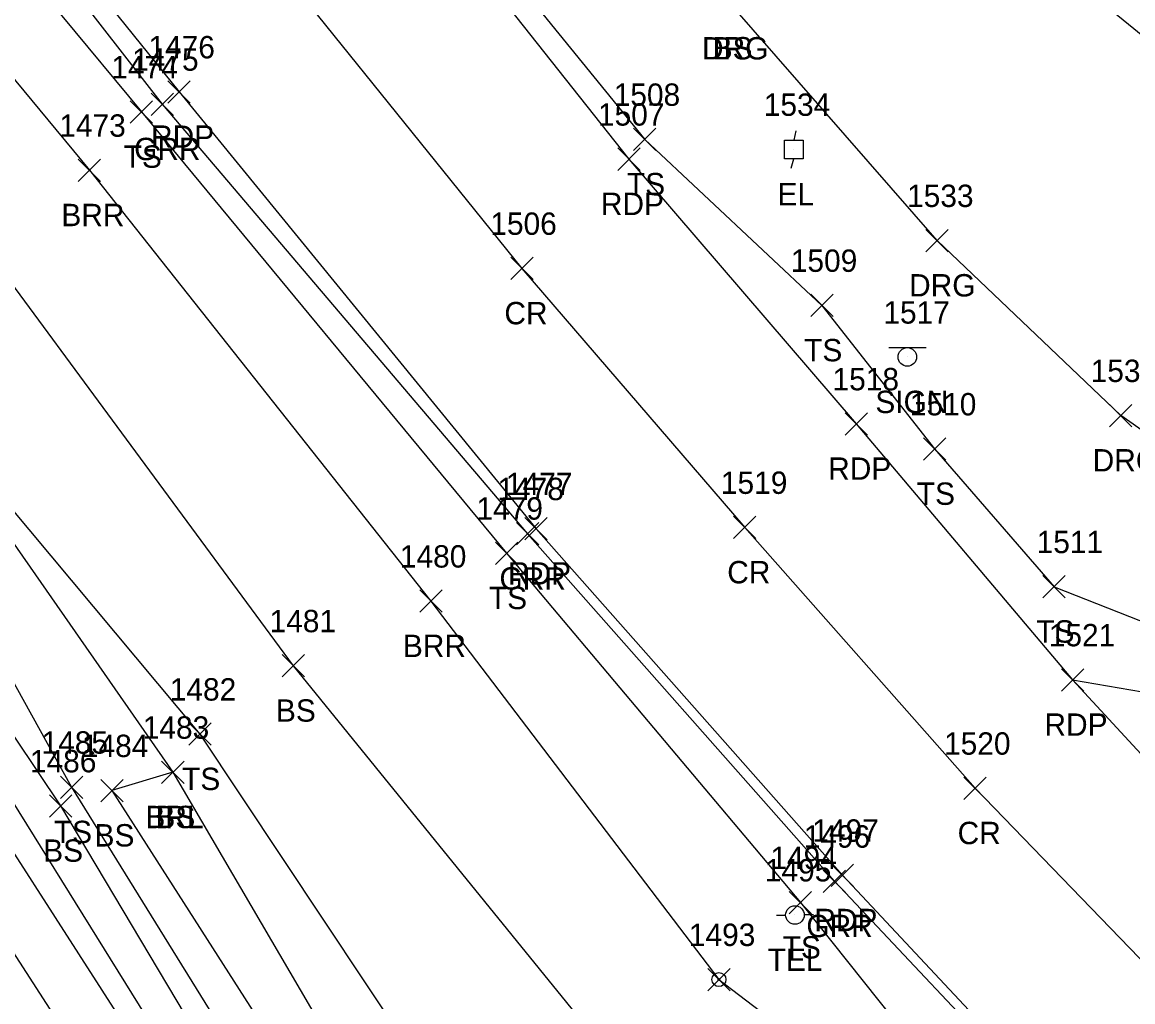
# Model space of a CAD drawing. Extents: x 1505656 to 1508446, y 700805 to 703031.
# Drawn here: x 1506356.7 to 1506456, y 702000.4 to 702088 of the extents above; entities that cross this region are included whole.
import ezdxf

# ---------------------------------------------------------------- set-up
doc = ezdxf.new("R2010")
doc.units = 0
for name, color, linetype in [('L_A', 7, 'Continuous'), ('L_I', 7, 'Continuous'), ('L_TIC', 7, 'Continuous'), ('LABL', 7, 'Continuous'), ('LELB', 7, 'Continuous'), ('P_A', 7, 'Continuous'), ('P_I', 7, 'Continuous'), ('P_TIC', 7, 'Continuous'), ('PET', 7, 'Continuous'), ('PRC', 7, 'Continuous'), ('R_A', 7, 'Continuous'), ('R_I', 7, 'Continuous'), ('R_TIC', 7, 'Continuous'), ('RDG', 7, 'Continuous'), ('RGR', 7, 'Continuous'), ('RR', 7, 'Continuous'), ('RRB', 7, 'Continuous'), ('S_A', 7, 'Continuous'), ('S_I', 7, 'Continuous'), ('SSGN', 7, 'Continuous'), ('U_A', 7, 'Continuous'), ('U_I', 7, 'Continuous'), ('UEPT', 7, 'Continuous'), ('UP', 7, 'Continuous'), ('UPGW', 7, 'Continuous')]:
    doc.layers.add(name, color=color, linetype=linetype)

msp = doc.modelspace()

# ---------------------------------------------------------------- linework, layer by layer
at = {"layer": 'L_TIC'}
for points in [[(1506366.336, 702078.99), (1506368.336, 702080.99)], [(1506368.336, 702078.99), (1506366.336, 702080.99)], [(1506411.366, 702076.53), (1506413.366, 702078.53)], [(1506413.366, 702076.53), (1506411.366, 702078.53)], [(1506361.684, 702073.768), (1506363.684, 702075.768)], [(1506363.684, 702073.768), (1506361.684, 702075.768)], [(1506427.221, 702061.685), (1506429.221, 702063.685)], [(1506429.221, 702061.685), (1506427.221, 702063.685)], [(1506437.306, 702048.851), (1506439.306, 702050.851)], [(1506439.306, 702048.851), (1506437.306, 702050.851)], [(1506399.017, 702039.528), (1506401.017, 702041.528)], [(1506401.017, 702039.528), (1506399.017, 702041.528)], [(1506447.995, 702036.533), (1506449.995, 702038.533)], [(1506449.995, 702036.533), (1506447.995, 702038.533)], [(1506392.244, 702035.244), (1506394.244, 702037.244)], [(1506394.244, 702035.244), (1506392.244, 702037.244)], [(1506379.93, 702029.463), (1506381.93, 702031.463)], [(1506381.93, 702029.463), (1506379.93, 702031.463)], [(1506371.567, 702023.35), (1506373.567, 702025.35)], [(1506373.567, 702023.35), (1506371.567, 702025.35)], [(1506369.149, 702019.942), (1506371.149, 702021.942)], [(1506371.149, 702019.942), (1506369.149, 702021.942)], [(1506369.149, 702019.942), (1506371.149, 702021.942)], [(1506371.149, 702019.942), (1506369.149, 702021.942)], [(1506360.093, 702018.604), (1506362.093, 702020.604)], [(1506362.093, 702018.604), (1506360.093, 702020.604)], [(1506363.703, 702018.302), (1506365.703, 702020.302)], [(1506365.703, 702018.302), (1506363.703, 702020.302)], [(1506359.109, 702016.936), (1506361.109, 702018.936)], [(1506361.109, 702016.936), (1506359.109, 702018.936)], [(1506425.305, 702008.283), (1506427.305, 702010.283)], [(1506427.305, 702008.283), (1506425.305, 702010.283)], [(1506418.011, 702001.404), (1506420.011, 702003.404)], [(1506420.011, 702001.404), (1506418.011, 702003.404)]]:
    msp.add_lwpolyline(points, dxfattribs=at)
at = {"layer": 'LABL'}
for points in [[(1506097.891, 702451.479), (1506093.586, 702448.306), (1506114.072, 702419.305), (1506137.715, 702376.045), (1506165.525, 702335.143), (1506176.551, 702314.381), (1506188.561, 702296.456), (1506197.642, 702285.718), (1506210.238, 702262.449), (1506236.391, 702222.105), (1506262.975, 702180.707), (1506287.878, 702142.766), (1506318.295, 702098.355), (1506343.911, 702058.606), (1506370.149, 702020.942), (1506392.925, 701982.024), (1506408.752, 701957.634), (1506404.597, 701955.648), (1506415.573, 701943.724), (1506429.754, 701925.555), (1506437.711, 701917.365), (1506453.701, 701897.967), (1506473.578, 701870.512), (1506501.095, 701826.995)], [(1506097.891, 702451.479), (1506119.326, 702422.589), (1506147.143, 702381.233), (1506170.739, 702339.268), (1506181.047, 702317.334), (1506195.309, 702300.853), (1506204.63, 702289.221), (1506217.936, 702268.002), (1506249.758, 702230.45), (1506275.61, 702192.019), (1506301.13, 702151.48), (1506333.13, 702110.445), (1506362.684, 702074.768), (1506393.244, 702036.244), (1506419.011, 702002.404), (1506440.789, 701985.798), (1506459.199, 701943.611), (1506474.51, 701912.206), (1506491.957, 701880.663), (1506505.674, 701860.234), (1506521.401, 701845.883), (1506529.177, 701832.12), (1506516.383, 701828.815), (1506501.095, 701826.995)]]:
    msp.add_lwpolyline(points, dxfattribs=at)
at = {"layer": 'LELB'}
for points in [[(1505941.536, 702671.126), (1505960.905, 702641.209), (1505983.848, 702606.414), (1506009.662, 702565.578), (1506036.171, 702525.552), (1506062.346, 702483.612), (1506087.3, 702443.663), (1506107.025, 702410.494), (1506132.096, 702372.933), (1506158.965, 702331.11), (1506171.726, 702310.513), (1506183.603, 702292.092), (1506190.679, 702281.135), (1506204.659, 702258.806), (1506230.375, 702218.876), (1506257.753, 702177.435), (1506282.281, 702138.539), (1506311.276, 702093.483), (1506337.325, 702051.881), (1506360.109, 702017.936), (1506385.569, 701975.184)], [(1506156.372, 702446.428), (1506184.163, 702403.933), (1506208.775, 702367.29), (1506232.272, 702331.602), (1506257.885, 702293.76), (1506284.653, 702254.182), (1506307.316, 702222.257), (1506327.162, 702194.165), (1506337.747, 702176.499), (1506365.447, 702137.462), (1506385.376, 702110.703), (1506412.366, 702077.53), (1506428.221, 702062.685), (1506438.306, 702049.851), (1506448.995, 702037.533), (1506458.547, 702033.774), (1506467.086, 702033.53), (1506475.874, 702037.864), (1506484.725, 702048.282), (1506486.521, 702060.251), (1506466.843, 702078.702), (1506445.767, 702095.887), (1506422.616, 702113.545), (1506407.805, 702126.816)], [(1506201.907, 702312.635), (1506228.688, 702274.023), (1506255.113, 702234.426), (1506278.209, 702201.234), (1506308.431, 702156.122), (1506338.791, 702114.368), (1506367.336, 702079.99), (1506400.017, 702040.528), (1506426.305, 702009.283), (1506443.257, 701988.04), (1506472.877, 701959.313), (1506500.815, 701931.78), (1506527.025, 701905.238), (1506551.996, 701883.977), (1506559.853, 701877.072), (1506564.801, 701867.875), (1506566.198, 701856.006), (1506560.037, 701843.77), (1506551.045, 701834.869), (1506537.765, 701828.439), (1506532.338, 701826.513)], [(1506188.561, 702296.456), (1506192.934, 702283.039), (1506207.332, 702260.501), (1506233.604, 702220.789), (1506259.915, 702179.297), (1506284.931, 702140.804), (1506313.826, 702095.76), (1506340.971, 702055.872), (1506361.093, 702019.604), (1506387.67, 701976.728), (1506404.597, 701955.648)], [(1506217.936, 702268.002), (1506241.751, 702226.262), (1506266.606, 702184.288), (1506291.505, 702144.914), (1506326.974, 702105.861), (1506352.657, 702068.74), (1506380.93, 702030.463), (1506410.258, 701994.342), (1506417.876, 701971.258), (1506422.757, 701954.376), (1506429.754, 701925.555), (1506435.035, 701911.198)], [(1506343.911, 702058.606), (1506372.567, 702024.35), (1506398.42, 701985.471), (1506414.884, 701960.491), (1506415.573, 701943.724)], [(1506370.149, 702020.942), (1506364.703, 702019.302), (1506390.538, 701978.915), (1506404.597, 701955.648)]]:
    msp.add_lwpolyline(points, dxfattribs=at)
at = {"layer": 'P_TIC'}
for points in [[(1506369.71, 702080.777), (1506371.71, 702082.777)], [(1506371.71, 702080.777), (1506369.71, 702082.777)], [(1506409.958, 702074.761), (1506411.958, 702076.761)], [(1506411.958, 702074.761), (1506409.958, 702076.761)], [(1506400.381, 702064.995), (1506402.381, 702066.995)], [(1506402.381, 702064.995), (1506400.381, 702066.995)], [(1506430.297, 702051.092), (1506432.297, 702053.092)], [(1506432.297, 702051.092), (1506430.297, 702053.092)], [(1506401.647, 702041.722), (1506403.647, 702043.722)], [(1506403.647, 702041.722), (1506401.647, 702043.722)], [(1506420.319, 702041.832), (1506422.319, 702043.832)], [(1506422.319, 702041.832), (1506420.319, 702043.832)], [(1506449.647, 702028.203), (1506451.647, 702030.203)], [(1506451.647, 702028.203), (1506449.647, 702030.203)], [(1506449.647, 702028.203), (1506451.647, 702030.203)], [(1506451.647, 702028.203), (1506449.647, 702030.203)], [(1506440.932, 702018.512), (1506442.932, 702020.512)], [(1506442.932, 702018.512), (1506440.932, 702020.512)], [(1506429.056, 702010.73), (1506431.056, 702012.73)], [(1506431.056, 702010.73), (1506429.056, 702012.73)]]:
    msp.add_lwpolyline(points, dxfattribs=at)
at = {"layer": 'PET'}
for points in [[(1506206.754, 702365.825), (1506229.985, 702330.468), (1506255.876, 702291.813), (1506281.674, 702252.742), (1506303.789, 702220.031), (1506334.98, 702175.126), (1506363.748, 702135.867), (1506383.847, 702109.99), (1506410.958, 702075.761), (1506431.297, 702052.092), (1506450.647, 702029.203), (1506469.416, 702008.908), (1506504.124, 701976.853), (1506522.626, 701959.501), (1506561.299, 701928.758), (1506582.882, 701911.403)], [(1506450.647, 702029.203), (1506459.006, 702027.774), (1506468.15, 702029.487), (1506475.625, 702033.452), (1506492.494, 702050.173), (1506506.996, 702065.686), (1506526.033, 702085.916), (1506543.399, 702101.888), (1506555.152, 702112.062), (1506575.485, 702129.802), (1506589.018, 702140.733), (1506620.875, 702167.685), (1506653.751, 702193.6), (1506674.556, 702208.994), (1506700.966, 702228.569), (1506728.002, 702249.615), (1506759.67, 702274.825), (1506793.399, 702301.372), (1506821.192, 702323.112), (1506840.119, 702337.397)], [(1506206.188, 702315.609), (1506232.667, 702276.153), (1506258.725, 702236.985), (1506281.311, 702203.576), (1506312.12, 702158.402), (1506342.493, 702116.71), (1506370.71, 702081.777), (1506402.647, 702042.722), (1506430.056, 702011.73), (1506447.463, 701993.175), (1506476.848, 701962.379), (1506503.963, 701935.538), (1506531.718, 701909.612)]]:
    msp.add_lwpolyline(points, dxfattribs=at)
at = {"layer": 'PRC'}
msp.add_lwpolyline([(1506142.566, 702437.634), (1506170.3, 702395.032), (1506195.332, 702357.442), (1506218.4, 702322.545), (1506244.279, 702283.748), (1506270.302, 702244.372), (1506292.293, 702211.79), (1506323.236, 702166.948), (1506353.008, 702126.877), (1506372.596, 702101.666), (1506401.381, 702065.995), (1506421.319, 702042.832), (1506441.932, 702019.512), (1506492.038, 701967.716), (1506516.184, 701946.542), (1506548.199, 701918.65), (1506563.792, 701905.332), (1506579.68, 701887.675), (1506594.041, 701864.962), (1506598.485, 701853.292), (1506603.081, 701837.538)], dxfattribs=at)
at = {"layer": 'R_TIC'}
for points in [[(1506368.199, 702079.673), (1506370.199, 702081.673)], [(1506370.199, 702079.673), (1506368.199, 702081.673)], [(1506437.535, 702067.484), (1506439.535, 702069.484)], [(1506439.535, 702067.484), (1506437.535, 702069.484)], [(1506453.96, 702051.835), (1506455.96, 702053.835)], [(1506455.96, 702051.835), (1506453.96, 702053.835)], [(1506400.884, 702041.274), (1506402.884, 702043.274)], [(1506402.884, 702041.274), (1506400.884, 702043.274)], [(1506428.345, 702010.198), (1506430.345, 702012.198)], [(1506430.345, 702010.198), (1506428.345, 702012.198)]]:
    msp.add_lwpolyline(points, dxfattribs=at)
at = {"layer": 'RDG'}
msp.add_lwpolyline([(1506467.151, 702044.283), (1506454.96, 702052.835), (1506438.535, 702068.484), (1506420.007, 702089.677), (1506396.605, 702114.721), (1506407.805, 702126.816), (1506403.566, 702132.716), (1506397.008, 702126.646), (1506385.476, 702138.66), (1506373.11, 702163.859), (1506354.572, 702195.797), (1506363.451, 702213.222), (1506370.892, 702223.454), (1506376.819, 702230.285), (1506393.449, 702217.001), (1506418.823, 702248.86), (1506438.366, 702232.018), (1506443.535, 702227.337), (1506453.597, 702221.015), (1506468.748, 702213.143)], dxfattribs=at)
at = {"layer": 'RGR'}
msp.add_lwpolyline([(1506194.429, 702325.739), (1506204.07, 702314.524), (1506231.72, 702275.449), (1506257.865, 702236.544), (1506280.914, 702202.923), (1506311.025, 702157.692), (1506341.898, 702115.676), (1506369.199, 702080.673), (1506401.884, 702042.274), (1506429.345, 702011.198), (1506447.039, 701992.434), (1506475.964, 701961.849), (1506503.455, 701934.999), (1506530.822, 701909.192), (1506554.476, 701886.522), (1506561.677, 701878.563), (1506566.908, 701868.507), (1506568.014, 701855.173), (1506562.315, 701841.05), (1506554.986, 701832.495), (1506533.66, 701824.882)], dxfattribs=at)
at = {"layer": 'RR'}
for points in [[(1506216.216, 702230.609), (1506241.138, 702191.913), (1506264.218, 702156.052), (1506289.374, 702116.983), (1506318.675, 702071.08), (1506345.503, 702029.867), (1506369.803, 701992.121), (1506395.941, 701951.532), (1506421.294, 701912.094)], [(1506212.178, 702227.875), (1506237.14, 702189.064), (1506259.993, 702153.601), (1506285.641, 702113.676), (1506314.244, 702068.629), (1506341.493, 702027.055), (1506364.792, 701991.038), (1506391.761, 701949.048), (1506416.431, 701910.499)]]:
    msp.add_lwpolyline(points, dxfattribs=at)
at = {"layer": 'RRB'}
msp.add_lwpolyline([(1506218.207, 702231.869), (1506243.423, 702192.986), (1506265.645, 702156.973), (1506291.152, 702118.107), (1506320.482, 702072.195), (1506347.645, 702031.42), (1506371.505, 701993.069), (1506397.737, 701952.642), (1506422.134, 701913.025), (1506446.302, 701877.372), (1506459.904, 701856.601), (1506479.197, 701826.274), (1506491.068, 701808.201), (1506507.805, 701783.164), (1506518.904, 701765.849), (1506532.833, 701744.112), (1506551.138, 701715.117), (1506563.365, 701695.789), (1506572.4, 701681.686), (1506577.693, 701674.709), (1506587.051, 701661.961)], dxfattribs=at)
at = {"layer": 'SSGN'}
for p, q in [((1506434.22, 702058.911), (1506437.553, 702058.911)), ((1506435.867, 702058.078), (1506435.867, 702058.078))]:
    msp.add_line(p, q, dxfattribs=at)
msp.add_circle((1506435.867, 702058.078), 0.833, dxfattribs=at)
at = {"layer": 'UEPT'}
for p, q in [((1506425.881, 702078.302), (1506425.714, 702077.469)), ((1506424.881, 702075.802), (1506424.881, 702077.469)), ((1506424.881, 702077.469), (1506426.548, 702077.469)), ((1506426.548, 702077.469), (1506426.548, 702075.802)), ((1506425.714, 702076.635), (1506425.714, 702076.635)), ((1506426.548, 702075.802), (1506424.881, 702075.802)), ((1506425.464, 702074.969), (1506425.714, 702075.802))]:
    msp.add_line(p, q, dxfattribs=at)
at = {"layer": 'UP'}
for p, q in [((1506424.152, 702008.172), (1506424.978, 702008.172)), ((1506425.811, 702008.178), (1506425.811, 702008.178)), ((1506427.478, 702008.178), (1506426.644, 702008.178)), ((1506426.644, 702008.178), (1506426.644, 702008.178)), ((1506427.478, 702008.178), (1506427.478, 702008.178))]:
    msp.add_line(p, q, dxfattribs=at)
msp.add_circle((1506425.811, 702008.178), 0.833, dxfattribs=at)
at = {"layer": 'UPGW'}
for radius in [0.625, 0.0833]:
    msp.add_circle((1506419.011, 702002.404), radius, dxfattribs=at)

# ---------------------------------------------------------------- texts
at = {"layer": 'L_A'}
for s, p in [('BS', (1506418.448, 702084.677)), ('TS', (1506365.746, 702074.99)), ('TS', (1506410.775, 702072.53)), ('BRR', (1506360.173, 702069.768)), ('TS', (1506426.631, 702057.685)), ('TS', (1506436.715, 702044.851)), ('TS', (1506398.426, 702035.528)), ('TS', (1506447.405, 702032.533)), ('BRR', (1506390.732, 702031.244)), ('BS', (1506379.371, 702025.463)), ('TS', (1506370.977, 702019.35)), ('BRL', (1506367.693, 702015.942)), ('BS', (1506368.59, 702015.942)), ('TS', (1506359.502, 702014.604)), ('BS', (1506363.144, 702014.302)), ('BS', (1506358.55, 702012.936)), ('TS', (1506424.714, 702004.283))]:
    msp.add_text(s, height=2, dxfattribs=at).set_placement(p)
at = {"layer": 'L_I'}
for s, p in [('1474', (1506364.644, 702082.99)), ('1508', (1506409.594, 702080.53)), ('1473', (1506359.991, 702077.768)), ('1509', (1506425.442, 702065.685)), ('1510', (1506436.093, 702052.851)), ('1479', (1506397.316, 702043.528)), ('1511', (1506447.436, 702040.533)), ('1480', (1506390.464, 702039.244)), ('1481', (1506378.804, 702033.463)), ('1482', (1506369.874, 702027.35)), ('1483', (1506367.456, 702023.942)), ('1483', (1506367.456, 702023.942)), ('1485', (1506358.4, 702022.604)), ('1484', (1506362.01, 702022.302)), ('1486', (1506357.361, 702020.936)), ('1494', (1506423.612, 702012.283)), ('1493', (1506416.318, 702005.404))]:
    msp.add_text(s, height=2, dxfattribs=at).set_placement(p)
at = {"layer": 'P_A'}
for s, p in [('RDP', (1506368.199, 702076.777)), ('RDP', (1506408.446, 702070.761)), ('CR', (1506399.814, 702060.995)), ('RDP', (1506428.785, 702047.092)), ('RDP', (1506400.135, 702037.722)), ('CR', (1506419.752, 702037.832)), ('RDP', (1506448.136, 702024.203)), ('RDP', (1506448.136, 702024.203)), ('CR', (1506440.365, 702014.512)), ('RDP', (1506427.545, 702006.73))]:
    msp.add_text(s, height=2, dxfattribs=at).set_placement(p)
at = {"layer": 'P_I'}
for s, p in [('1476', (1506367.962, 702084.777)), ('1507', (1506408.186, 702078.761)), ('1506', (1506398.554, 702068.995)), ('1518', (1506429.171, 702055.092)), ('1477', (1506399.954, 702045.722)), ('1519', (1506419.185, 702045.832)), ('1521', (1506448.521, 702032.203)), ('1521', (1506448.521, 702032.203)), ('1520', (1506439.152, 702022.512)), ('1497', (1506427.363, 702014.73))]:
    msp.add_text(s, height=2, dxfattribs=at).set_placement(p)
at = {"layer": 'R_A'}
for s, p in [('DRG', (1506417.495, 702084.677)), ('GRR', (1506366.687, 702075.673)), ('DRG', (1506436.023, 702063.484)), ('DRG', (1506452.449, 702047.835)), ('GRR', (1506399.373, 702037.274)), ('GRR', (1506426.833, 702006.198))]:
    msp.add_text(s, height=2, dxfattribs=at).set_placement(p)
at = {"layer": 'R_I'}
for s, p in [('1475', (1506366.506, 702083.673)), ('1533', (1506435.842, 702071.484)), ('1532', (1506452.268, 702055.835)), ('1478', (1506399.191, 702045.274)), ('1496', (1506426.597, 702014.198))]:
    msp.add_text(s, height=2, dxfattribs=at).set_placement(p)
at = {"layer": 'S_A'}
msp.add_text('SIGN', height=2, dxfattribs=at).set_placement((1506433.005, 702053.057))
at = {"layer": 'S_I'}
msp.add_text('1517', height=2, dxfattribs=at).set_placement((1506433.721, 702061.057))
at = {"layer": 'U_A'}
for s, p in [('EL', (1506424.25, 702071.635)), ('TEL', (1506423.37, 702003.178))]:
    msp.add_text(s, height=2, dxfattribs=at).set_placement(p)
at = {"layer": 'U_I'}
for s, p in [('1534', (1506423.022, 702079.635)), ('1495', (1506423.118, 702011.178)), ('1493', (1506416.318, 702005.404))]:
    msp.add_text(s, height=2, dxfattribs=at).set_placement(p)

doc.saveas('drawing.dxf')
